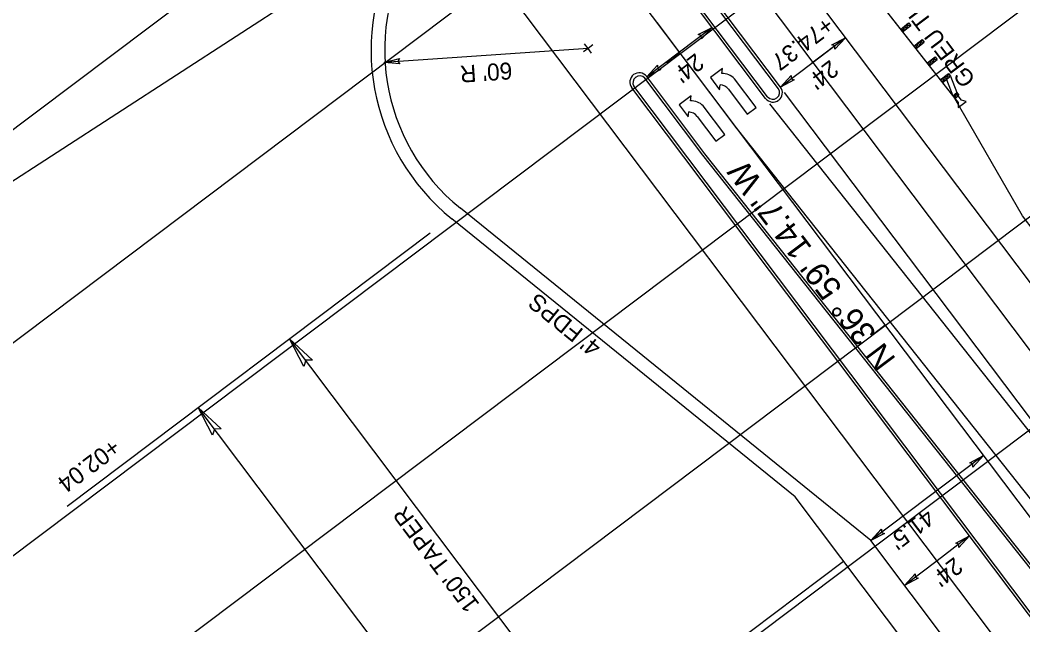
# Model space of a CAD drawing. Extents: x 1262309 to 1264352, y 775189 to 777755.
# Drawn here: x 1262668.6 to 1262963, y 777083.2 to 777260.9 of the extents above; entities that cross this region are included whole.
import ezdxf

# ---------------------------------------------------------------- set-up
doc = ezdxf.new("R2010")
doc.units = 0
for name, color, linetype in [('Default', 7, 'Continuous'), ('Prop Conc 5in Monolithic Keyed In Island', 7, 'Continuous'), ('Prop Dimension', 7, 'Continuous'), ('Prop Dimension Text', 7, 'Continuous'), ('Prop EOT', 7, 'Continuous'), ('Prop Guardrail Anchor Unit CELL', 7, 'Continuous'), ('Prop Horizontal Alignment', 7, 'Continuous'), ('Prop Horizontal Alignment Direction Label', 7, 'Continuous'), ('Prop Horizontal Alignment Station Label', 7, 'Continuous'), ('Prop Horizontal Alignment Tick Small', 7, 'Continuous'), ('Prop Lane Arrow CELL', 7, 'Continuous'), ('Prop Lane Lines', 7, 'Continuous'), ('Prop Paved Shoulder', 7, 'Continuous'), ('Prop Terminator CELL', 7, 'Continuous'), ('Scratch_Level_3', 7, 'Continuous')]:
    doc.layers.add(name, color=color, linetype=linetype)

msp = doc.modelspace()

# ---------------------------------------------------------------- linework, layer by layer
at = {"layer": 'Default'}
for p, q in [((1262862.45, 777251.13), (1262862.45, 777251.13)), ((1262862.45, 777251.13), (1262862.45, 777251.13)), ((1262922.61, 777171.25), (1262922.61, 777171.25)), ((1262922.61, 777171.25), (1262922.61, 777171.25))]:
    msp.add_line(p, q, dxfattribs=at)
at = {"layer": 'Prop Conc 5in Monolithic Keyed In Island'}
for p, q in [((1262891.25, 777240.73), (1262829.24, 777323.06)), ((1262888.06, 777238.32), (1262846.5, 777293.5)), ((1262849.17, 777244.25), (1262849.16, 777244.25)), ((1262965.39, 777086.61), (1262848.77, 777241.45)), ((1262869.07, 777221.15), (1262851.98, 777243.84)), ((1262971.72, 777091.5), (1262869.06, 777221.16))]:
    msp.add_line(p, q, dxfattribs=at)
for centre, radius, start, end in [((1262850.52, 777242.44), 2.02, 43.8104, 209.5292), ((1262889.59, 777239.61), 2, 220.3839, 33.8774)]:
    msp.add_arc(centre, radius, start, end, dxfattribs=at)
at = {"layer": 'Prop Dimension'}
for p, q in [((1262835.36, 777252.56), (1262834.33, 777253.92)), ((1262836.72, 777253.58), (1262835.36, 777252.56)), ((1262835.36, 777252.56), (1262775.5, 777248.44)), ((1262835.36, 777252.56), (1262833.99, 777251.53)), ((1262836.38, 777251.19), (1262835.36, 777252.56)), ((1262951.47, 777132.94), (1262918.32, 777107.97))]:
    msp.add_line(p, q, dxfattribs=at)
at = {"layer": 'Prop Dimension Text'}
for p, q in [((1262871.74, 777258.74), (1262862.18, 777251.48)), ((1262910.95, 777255.71), (1262901.06, 777248.19)), ((1262910.95, 777255.71), (1262901.4, 777248.45)), ((1262862.18, 777251.48), (1262852.63, 777244.21)), ((1262901.4, 777248.45), (1262891.85, 777241.18)), ((1262682.4, 777118.06), (1262789.02, 777198.37)), ((1262837.95, 777047.44), (1262747.7, 777167.25)), ((1262875.57, 776941.71), (1262720.9, 777147.06)), ((1262947.34, 777109.34), (1262937.79, 777102.07)), ((1262834.45, 777044.8), (1262910.33, 777101.95)), ((1262937.79, 777102.07), (1262928.23, 777094.81))]:
    msp.add_line(p, q, dxfattribs=at)
for points in [[(1262867.69, 777256.64), (1262871.74, 777258.74), (1262868.62, 777255.37), (1262868.59, 777256.35)], [(1262906.9, 777253.61), (1262910.95, 777255.71), (1262907.83, 777252.34), (1262907.81, 777253.32)], [(1262906.9, 777253.61), (1262910.95, 777255.71), (1262907.83, 777252.34), (1262907.81, 777253.32)], [(1262856.68, 777246.32), (1262852.63, 777244.21), (1262855.75, 777247.59), (1262855.78, 777246.6)], [(1262895.9, 777243.29), (1262891.85, 777241.18), (1262894.96, 777244.56), (1262894.99, 777243.58)], [(1262751.88, 777159.13), (1262747.7, 777167.25), (1262754.43, 777160.99), (1262752.46, 777160.94)], [(1262725.07, 777138.94), (1262720.9, 777147.06), (1262727.62, 777140.79), (1262725.65, 777140.75)], [(1262947.42, 777130.83), (1262951.47, 777132.94), (1262948.35, 777129.56), (1262948.33, 777130.55)], [(1262922.37, 777110.08), (1262918.32, 777107.97), (1262921.44, 777111.35), (1262921.47, 777110.36)], [(1262943.29, 777107.23), (1262947.34, 777109.34), (1262944.22, 777105.96), (1262944.19, 777106.95)], [(1262932.28, 777096.92), (1262928.23, 777094.81), (1262931.35, 777098.19), (1262931.38, 777097.2)]]:
    msp.add_lwpolyline(points, close=True, dxfattribs=at)
at = {"layer": 'Prop EOT'}
for p, q in [((1262887.46, 777237.86), (1262845.9, 777293.05)), ((1262869.65, 777221.63), (1262852.56, 777244.31)), ((1263001.9, 777036.9), (1262848.17, 777241)), ((1263010.68, 777043.51), (1262869.65, 777221.63)), ((1262918.32, 777107.97), (1262797.85, 777205.59)), ((1263058.9, 776921.33), (1262918.32, 777107.97))]:
    msp.add_line(p, q, dxfattribs=at)
for points in [[(1262965.52, 777183.26), (1262848.98, 777337.98)], [(1262891.85, 777241.18), (1262829.84, 777323.51)]]:
    msp.add_lwpolyline(points, dxfattribs=at)
for centre, radius, start, end in [((1262835.62, 777252.21), 60, 147.262, 230.9826), ((1262850.37, 777242.65), 2.75, 126.9874, 216.9874), ((1262850.37, 777242.66), 2.74, 36.9874, 126.9874), ((1262889.65, 777239.53), 2.75, 306.9874, 36.9874), ((1262889.65, 777239.51), 2.74, 216.9874, 306.9874)]:
    msp.add_arc(centre, radius, start, end, dxfattribs=at)
at = {"layer": 'Prop Guardrail Anchor Unit CELL'}
for p, q in [((1262913.83, 777275.03), (1262942.69, 777238.26)), ((1262927.07, 777258.16), (1262929.46, 777260.04)), ((1262927.69, 777257.38), (1262930.07, 777259.25)), ((1262928.26, 777259.1), (1262927.69, 777257.38)), ((1262930.07, 777259.25), (1262928.26, 777259.1)), ((1262928.26, 777259.1), (1262928.88, 777258.31)), ((1262928.88, 777258.31), (1262929.46, 777260.04)), ((1262929.46, 777260.04), (1262930.07, 777259.25)), ((1262927.07, 777258.16), (1262928.88, 777258.31)), ((1262927.07, 777258.16), (1262927.69, 777257.38)), ((1262930.96, 777253.21), (1262933.43, 777255.14)), ((1262930.96, 777253.21), (1262932.81, 777253.39)), ((1262931.58, 777252.42), (1262934.05, 777254.36)), ((1262932.19, 777254.17), (1262931.58, 777252.42)), ((1262934.05, 777254.36), (1262932.19, 777254.17)), ((1262932.19, 777254.17), (1262932.81, 777253.39)), ((1262932.81, 777253.39), (1262933.43, 777255.14)), ((1262933.43, 777255.14), (1262934.05, 777254.36)), ((1262934.85, 777248.25), (1262937.21, 777250.1)), ((1262936.65, 777248.39), (1262937.21, 777250.1)), ((1262937.21, 777250.1), (1262937.83, 777249.32)), ((1262934.85, 777248.25), (1262936.65, 777248.39)), ((1262935.47, 777247.46), (1262937.83, 777249.32)), ((1262936.03, 777249.18), (1262935.47, 777247.46)), ((1262937.83, 777249.32), (1262936.03, 777249.18)), ((1262936.03, 777249.18), (1262936.65, 777248.39)), ((1262938.74, 777243.29), (1262941.15, 777245.18)), ((1262939.36, 777242.51), (1262941.77, 777244.4)), ((1262939.95, 777244.24), (1262939.36, 777242.51)), ((1262941.77, 777244.4), (1262939.95, 777244.24)), ((1262939.95, 777244.24), (1262940.56, 777243.45)), ((1262940.56, 777243.45), (1262941.15, 777245.18)), ((1262941.15, 777245.18), (1262941.77, 777244.4)), ((1262941.77, 777244.4), (1262943.57, 777239.58)), ((1262938.74, 777243.29), (1262940.56, 777243.45)), ((1262940.56, 777243.45), (1262942.39, 777238.65)), ((1262942.39, 777238.65), (1262943.57, 777239.58)), ((1262944.18, 777238.79), (1262942.39, 777238.65)), ((1262943.26, 777238.65), (1262942.77, 777238.28)), ((1262942.77, 777238.28), (1262944.01, 777236.65)), ((1262943, 777237.86), (1262943.57, 777239.58)), ((1262943, 777237.86), (1262944.18, 777238.79)), ((1262943.75, 777239.02), (1262943.26, 777238.65)), ((1262943.57, 777239.58), (1262943.87, 777239.18)), ((1262943.57, 777239.58), (1262944.18, 777238.79)), ((1262944.98, 777237.38), (1262943.75, 777239.02)), ((1262944.01, 777236.65), (1262944.03, 777235.19)), ((1262944.03, 777235.19), (1262946.38, 777236.96)), ((1262946.38, 777236.96), (1262944.98, 777237.38))]:
    msp.add_line(p, q, dxfattribs=at)
at = {"layer": 'Prop Horizontal Alignment'}
msp.add_line((1263127.22, 776899.61), (1262639.84, 777546.67), dxfattribs=at)
at = {"layer": 'Prop Horizontal Alignment Station Label'}
msp.add_line((1262632.6, 777191.78), (1262792.29, 777295.24), dxfattribs=at)
at = {"layer": 'Prop Horizontal Alignment Tick Small'}
for p, q in [((1262862.45, 777251.13), (1262858.46, 777248.12)), ((1262922.61, 777171.25), (1262918.62, 777168.24))]:
    msp.add_line(p, q, dxfattribs=at)
at = {"layer": 'Prop Lane Arrow CELL'}
for p, q in [((1262874.8, 777246.62), (1262871.26, 777244.02)), ((1262871.26, 777244.02), (1262873.92, 777240.39)), ((1262874.59, 777245.15), (1262874.8, 777246.62)), ((1262873.92, 777240.39), (1262874.13, 777241.86)), ((1262884.69, 777235.23), (1262878.35, 777243.66)), ((1262865.6, 777238.64), (1262862.06, 777236.03)), ((1262865.4, 777237.17), (1262865.6, 777238.64)), ((1262876.55, 777240.56), (1262882.06, 777233.25)), ((1262862.06, 777236.03), (1262864.73, 777232.41)), ((1262875.5, 777227.25), (1262869.15, 777235.68)), ((1262882.06, 777233.25), (1262884.69, 777235.23)), ((1262864.73, 777232.41), (1262864.93, 777233.88)), ((1262867.36, 777232.58), (1262872.86, 777225.27)), ((1262872.86, 777225.27), (1262875.5, 777227.25))]:
    msp.add_line(p, q, dxfattribs=at)
for centre, radius, start, end in [((1262874.69, 777239.91), 5.25, 45.6635, 90.9752), ((1262873.94, 777238.61), 3.27, 36.9874, 86.6456), ((1262865.49, 777231.93), 5.25, 45.6635, 90.9752), ((1262864.75, 777230.62), 3.27, 36.9874, 86.6456)]:
    msp.add_arc(centre, radius, start, end, dxfattribs=at)
at = {"layer": 'Prop Lane Lines'}
for p, q in [((1263348.11, 776655.37), (1262839.39, 777330.78)), ((1262879.16, 777228.94), (1262855.67, 777260.13)), ((1263029.85, 777057.97), (1262893.05, 777239.58)), ((1263027.05, 777061.68), (1262893.05, 777239.58)), ((1263029.77, 777058.06), (1262888.66, 777236.27)), ((1263020.37, 777050.61), (1262879.25, 777228.82))]:
    msp.add_line(p, q, dxfattribs=at)
msp.add_lwpolyline([(1263120.31, 776859.74), (1262792.29, 777295.24)], dxfattribs=at)
at = {"layer": 'Prop Paved Shoulder'}
for p, q in [((1262913.85, 777275.05), (1262943, 777237.86)), ((1262962.91, 777203.4), (1262943, 777237.86)), ((1262988.25, 777169.71), (1262962.91, 777203.4)), ((1262896.15, 777120.79), (1262795.33, 777202.48)), ((1263065.65, 776895.74), (1262896.15, 777120.79))]:
    msp.add_line(p, q, dxfattribs=at)
msp.add_arc((1262835.62, 777252.21), 64, 149.7341, 230.9826, dxfattribs=at)
at = {"layer": 'Prop Terminator CELL'}
for points in [[(1262780.04, 777247.98), (1262775.5, 777248.44), (1262779.96, 777249.55), (1262779.44, 777248.71)], [(1262947.41, 777130.85), (1262951.47, 777132.94), (1262948.34, 777129.58), (1262948.32, 777130.56)], [(1262922.38, 777110.06), (1262918.32, 777107.97), (1262921.45, 777111.33), (1262921.48, 777110.35)]]:
    msp.add_lwpolyline(points, close=True, dxfattribs=at)
at = {"layer": 'Scratch_Level_3'}
for p, q in [((1262604.35, 777181.92), (1263099.45, 777554.83)), ((1262634.43, 777141.98), (1263129.53, 777514.89)), ((1262664.51, 777102.04), (1263159.61, 777474.95)), ((1262694.59, 777062.1), (1263189.7, 777435.02)), ((1262724.68, 777022.16), (1263219.78, 777395.08)), ((1262754.76, 776982.22), (1263249.86, 777355.14))]:
    msp.add_line(p, q, dxfattribs=at)

# ---------------------------------------------------------------- texts
at = {"layer": 'Prop Dimension Text'}
for s, rotation, p in [('+74.37', 216.9874, (1262905.15, 777262.14)), ("24'", 217.2584, (1262866.91, 777251.36)), ("60' R", 183.9296, (1262812.92, 777248.51)), ("24'", 217.2584, (1262906.42, 777249.39)), ("4' FDPS", 140.9826, (1262839.6, 777165.45)), ('+02.04', 216.9874, (1262695.61, 777138.17)), ("150' TAPER", 126.9874, (1262803.68, 777089.27)), ("41.5'", 217.2584, (1262934.65, 777117.57)), ("24'", 217.2584, (1262942.88, 777103.35))]:
    msp.add_text(s, height=5, rotation=rotation, dxfattribs=at).set_placement(p)
at = {"layer": 'Prop Guardrail Anchor Unit CELL'}
msp.add_text('GREU TL-3', height=5, rotation=126.9874, dxfattribs=at).set_placement((1262949.33, 777243.5))
at = {"layer": 'Prop Horizontal Alignment Direction Label'}
msp.add_text('N 36%%d 59\' 14.7" W', height=7, rotation=126.9874, dxfattribs=at).set_placement((1262925.93, 777161.27))

doc.saveas('drawing.dxf')
